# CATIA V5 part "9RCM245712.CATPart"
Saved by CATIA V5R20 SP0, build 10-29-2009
Part number: 9RCM245712
Revision: ANY
Definition: UNKNOWN
Nomenclature: 9RCM245712
Source: Unknown
Bounding box of the stored display mesh (mm): x -45 to 11.95, y -11.95 to 11.95, z -4.8 to 4.8
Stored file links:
  C:\Users\Utente\Desktop\IO LAVORO\3D X SITO CF\CUMSA\3D files RCM\RCM 245712\9RCM245712.CATPart
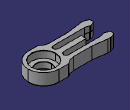
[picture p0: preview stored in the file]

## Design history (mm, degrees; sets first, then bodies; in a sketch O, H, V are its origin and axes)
Body1 "Chaflán2" (main body)
  Solid1: solid without history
